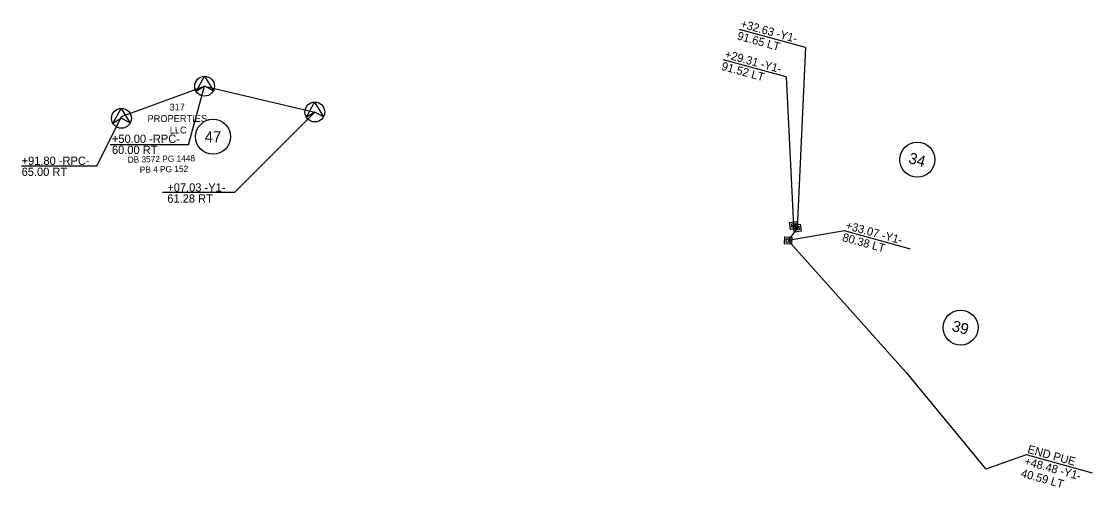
# Model space of a CAD drawing. Extents: x 1638966 to 1642158, y 841755 to 844938.
# Drawn here: x 1641382 to 1642158, y 841755 to 842092 of the extents above; entities that cross this region are included whole.
import ezdxf

# ---------------------------------------------------------------- set-up
doc = ezdxf.new("R2010")
doc.units = 0
for name, color, linetype in [('Exist Building', 7, 'Continuous'), ('Exist Guardrail Text', 7, 'Continuous'), ('Exist Property Owner Text', 7, 'Continuous'), ('Exist Structure Minor Pipes CMP 24 Inch', 7, 'Continuous'), ('Exist Structure Minor Pipes RCP 24 Inch', 7, 'Continuous'), ('P_RDY_ROW_RW_CA_Lines', 7, 'Continuous'), ('Prop ROW Marker CELL', 7, 'Continuous')]:
    doc.layers.add(name, color=color, linetype=linetype)

msp = doc.modelspace()

# ---------------------------------------------------------------- linework, layer by layer
at = {"layer": 'Exist Building'}
for centre, radius in [((1641520.48, 842008.71), 12.66), ((1642031.07, 841992.05), 12.73), ((1642062.39, 841870.48), 12.69)]:
    msp.add_circle(centre, radius, dxfattribs=at)
at = {"layer": 'Exist Guardrail Text'}
for p, q in [((1641502.65, 842002.87), (1641445.97, 842002.87)), ((1641436.46, 841987.32), (1641381.59, 841987.32)), ((1641536.11, 841968.2), (1641483.82, 841968.2))]:
    msp.add_line(p, q, dxfattribs=at)
for points in [[(1641502.65, 842002.87), (1641514.38, 842045.31)], [(1641436.32, 841987.32), (1641454.07, 842023.27)], [(1641536.11, 841968.2), (1641594.3, 842026.63)]]:
    msp.add_lwpolyline(points, dxfattribs=at)
at = {"layer": 'Exist Structure Minor Pipes CMP 24 Inch'}
for p, q in [((1641950.03, 842073.29), (1641902.04, 842086.5)), ((1641935.86, 842052.07), (1641890.64, 842064.51)), ((1642026.22, 841927.31), (1641978.23, 841940.52)), ((1642158.11, 841765.1), (1642110.12, 841778.31))]:
    msp.add_line(p, q, dxfattribs=at)
for points in [[(1641950.03, 842073.29), (1641944.05, 841942.52)], [(1641935.86, 842052.07), (1641941.38, 841944.49)], [(1641978.23, 841940.52), (1641937.35, 841933.45)], [(1642110, 841778.34), (1642080.63, 841767.76)]]:
    msp.add_lwpolyline(points, dxfattribs=at)
at = {"layer": 'Exist Structure Minor Pipes RCP 24 Inch'}
for p, q in [((1641941.38, 841944.49), (1641944.05, 841942.52)), ((1641941.38, 841944.49), (1641941.38, 841944.49)), ((1641944.05, 841942.52), (1641937.35, 841933.45)), ((1641944.05, 841942.52), (1641944.05, 841942.52)), ((1641937.35, 841933.45), (1642023.05, 841837.83)), ((1641937.35, 841933.45), (1641937.35, 841933.45)), ((1642023.05, 841837.83), (1642080.63, 841767.76))]:
    msp.add_line(p, q, dxfattribs=at)
for points in [[(1641938.48, 841946.63), (1641943.52, 841947.39), (1641944.27, 841942.35), (1641939.24, 841941.6)], [(1641939.93, 841945.56), (1641942.45, 841945.94), (1641942.82, 841943.42), (1641940.31, 841943.04)], [(1641941.15, 841944.66), (1641946.19, 841945.41), (1641946.94, 841940.38), (1641941.91, 841939.62)], [(1641942.6, 841943.59), (1641945.12, 841943.96), (1641945.49, 841941.45), (1641942.98, 841941.07)], [(1641934.94, 841936.13), (1641940.03, 841935.85), (1641939.75, 841930.77), (1641934.67, 841931.05)], [(1641936.14, 841934.79), (1641938.69, 841934.65), (1641938.55, 841932.11), (1641936.01, 841932.25)]]:
    msp.add_lwpolyline(points, close=True, dxfattribs=at)
at = {"layer": 'P_RDY_ROW_RW_CA_Lines'}
for p, q in [((1641454.07, 842023.27), (1641514.38, 842045.31)), ((1641514.38, 842045.31), (1641594.3, 842026.63))]:
    msp.add_line(p, q, dxfattribs=at)
at = {"layer": 'Prop ROW Marker CELL'}
for p, q in [((1641508.22, 842041.56), (1641514.21, 842052.51)), ((1641514.38, 842045.31), (1641508.22, 842041.56)), ((1641514.21, 842052.51), (1641520.72, 842041.86)), ((1641520.72, 842041.86), (1641514.38, 842045.31)), ((1641588.13, 842022.88), (1641594.12, 842033.83)), ((1641594.12, 842033.83), (1641600.63, 842023.18)), ((1641447.94, 842018.32), (1641453.93, 842029.27)), ((1641454.1, 842022.07), (1641447.94, 842018.32)), ((1641453.93, 842029.27), (1641460.44, 842018.62)), ((1641460.44, 842018.62), (1641454.1, 842022.07)), ((1641594.3, 842026.63), (1641588.13, 842022.88)), ((1641600.63, 842023.18), (1641594.3, 842026.63))]:
    msp.add_line(p, q, dxfattribs=at)
for centre in [(1641514.38, 842045.31), (1641594.3, 842026.63), (1641454.1, 842022.07)]:
    msp.add_circle(centre, 7.2, dxfattribs=at)

# ---------------------------------------------------------------- texts
at = {"layer": 'Exist Building'}
for s, rotation, p in [('47', 360, (1641514.52, 842004.71)), ('34', 344.6135, (1642024.18, 841989.79)), ('39', 344.6135, (1642055.55, 841868.21))]:
    msp.add_text(s, height=8, rotation=rotation, dxfattribs=at).set_placement(p)
at = {"layer": 'Exist Guardrail Text'}
for s, p in [('+50.00 -RPC-', (1641447.21, 842004.25)), ('60.00 RT', (1641447.21, 841996.25)), ('+91.80 -RPC-', (1641381.73, 841988.32)), ('65.00 RT', (1641381.73, 841980.32)), ('+07.03 -Y1-', (1641487.35, 841968.97)), ('61.28 RT', (1641487.35, 841960.97))]:
    msp.add_text(s, height=6, dxfattribs=at).set_placement(p)
at = {"layer": 'Exist Property Owner Text'}
for s, height, rotation, p in [('317 ', 5, 0.22884, (1641488.94, 842027.71)), ('PROPERTIES ', 5, 0.22884, (1641473.02, 842019.31)), ('LLC', 5, 0.22884, (1641489.13, 842011.04)), ('DB 3572 PG 1448', 4.5, 1.28298, (1641458.68, 841989.85)), ('PB 4 PG 152', 4.5, 1.28298, (1641467.42, 841982.54))]:
    msp.add_text(s, height=height, rotation=rotation, dxfattribs=at).set_placement(p)
at = {"layer": 'Exist Structure Minor Pipes CMP 24 Inch'}
for s, p in [('+32.63 -Y1-', (1641902.44, 842087.94)), ('91.65 LT', (1641900.05, 842079.26)), ('+29.31 -Y1-', (1641891.03, 842065.96)), ('91.52 LT', (1641888.65, 842057.28)), ('+33.07 -Y1-', (1641978.63, 841941.96)), ('80.38 LT', (1641976.24, 841933.29)), ('END PUE', (1642110.52, 841779.76)), ('+48.48 -Y1-', (1642108.13, 841771.08)), ('40.59 LT', (1642105.74, 841762.4))]:
    msp.add_text(s, height=6, rotation=344.6135, dxfattribs=at).set_placement(p)

doc.saveas('drawing.dxf')
